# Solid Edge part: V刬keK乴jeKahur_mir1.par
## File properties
Last saved by: Egon 815
Revision: 53
Accuracy: 0,990
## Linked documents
ljeKahur.par
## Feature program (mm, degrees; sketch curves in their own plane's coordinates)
part copy "CopiedPart_1"
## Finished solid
Body 1: solid body, 18 faces, 34 edges, 18 vertices.
  Faces by surface: plane 11, cone 3, cylinder 2, spline 2
  Edges by curve: line 14, circle 11, curve on surface 7, intersection 2
Bounding box of the edges (mm; curved faces can reach further): 2182.208 x 5485.690 x 2152.254, from (10802.6405, 23199.3222, 5032.5774) to (12984.8483, 28685.0118, 7184.8312).
Cylindrical faces by radius (mm): R125 x1, R1091.1039 x1
Conical faces (half-angle, radius in mm at the cone's reference point): 45 deg R1091.1039 x3
Planar faces by outward normal: +x 1, +y 4, +z 2, -x 1, -z 2, oblique 1
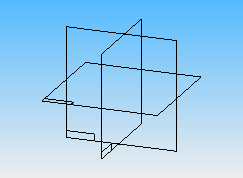
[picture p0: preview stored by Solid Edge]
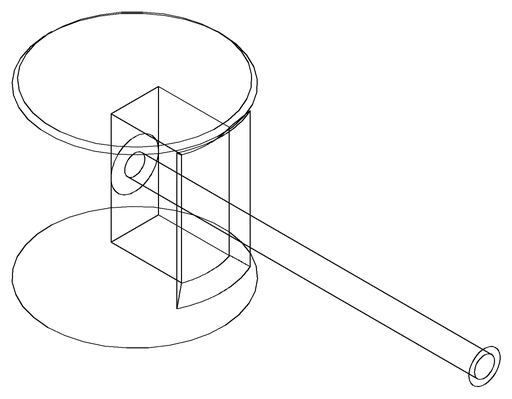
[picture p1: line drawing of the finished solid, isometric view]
